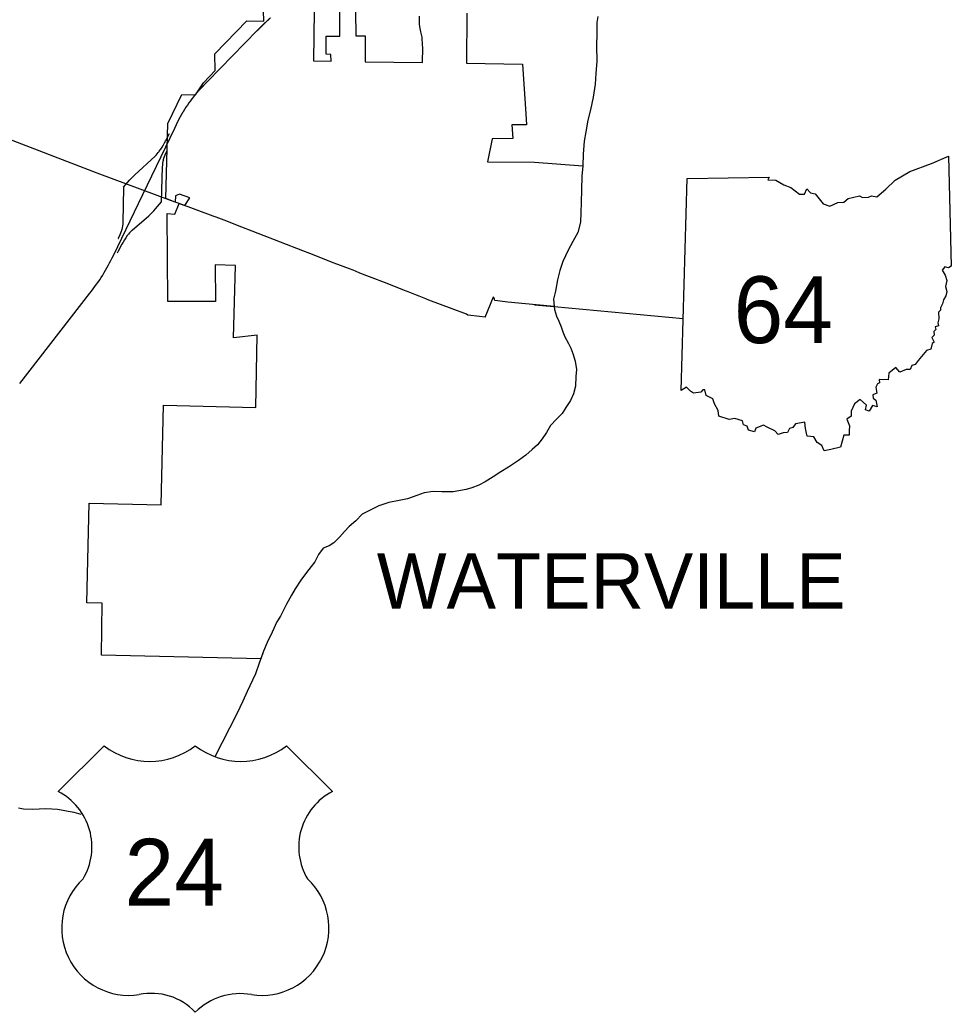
# Model space of a CAD drawing. Extents: x 0 to 750, y 0 to 507.
# Drawn here: x 196.4 to 259.5, y 82 to 149.3 of the extents above; entities that cross this region are included whole.
import ezdxf

# ---------------------------------------------------------------- set-up
doc = ezdxf.new("R2010")
doc.units = 0
for name, color, linetype in [('DV_X_Corp_Line', 7, 'Continuous'), ('GM_X_Corporation_Text', 7, 'Continuous'), ('GM_X_County', 7, 'Continuous'), ('GM_X_Rail_Line', 7, 'Continuous'), ('GM_X_State_Route', 7, 'Continuous'), ('GM_X_US_Route', 7, 'Continuous'), ('PV_P_Text', 7, 'Continuous')]:
    doc.layers.add(name, color=color, linetype=linetype)

msp = doc.modelspace()

# ---------------------------------------------------------------- linework, layer by layer
at = {"layer": 'DV_X_Corp_Line'}
for points in [[(226.679, 149.758), (226.646, 146.356), (230.442, 146.297), (230.68, 142.921), (230.706, 142.191), (229.73, 142.174), (229.795, 141.25), (228.396, 141.225), (228.067, 139.675), (231.248, 139.656), (234.535, 139.41), (234.462, 138.714), (234.446, 137.771), (234.417, 136.918), (234.394, 136.251), (234.376, 135.594), (234.203, 134.894), (233.846, 134.281), (233.544, 133.677), (233.186, 132.909), (232.969, 132.299), (232.806, 131.664), (232.673, 130.908), (232.541, 130.358), (232.595, 129.859), (232.617, 129.656), (232.755, 129.217), (232.895, 128.879), (233.058, 128.484), (233.178, 128.141), (233.323, 127.802), (233.566, 127.361), (233.721, 127.053), (233.865, 126.679), (234.002, 126.169), (234.092, 125.606), (234.069, 125.124), (234.028, 124.467), (233.889, 123.938), (233.695, 123.484), (233.371, 123.013), (233.129, 122.615), (232.756, 122.22), (232.348, 121.795), (232.079, 121.318), (231.766, 120.892), (231.453, 120.495), (231.102, 120.18), (230.669, 119.781), (230.162, 119.428), (229.492, 118.977), (228.98, 118.655), (228.463, 118.317), (227.916, 117.98), (227.481, 117.751), (227.017, 117.573), (226.629, 117.465), (225.754, 117.309), (224.977, 117.307), (224.385, 117.332), (223.787, 117.241), (223.283, 117.054), (222.647, 116.834), (222.094, 116.708), (221.384, 116.569), (220.709, 116.355), (220.077, 116.034), (219.581, 115.781), (219.137, 115.332), (218.69, 114.958), (218.388, 114.617), (218.05, 114.231), (217.653, 113.851), (217.339, 113.646), (216.94, 113.477), (216.621, 113.045), (216.358, 112.563), (216.111, 112.231), (215.803, 111.824), (215.419, 111.309), (215.033, 110.723), (214.79, 110.306), (214.449, 109.689), (214.034, 108.878), (213.801, 108.48), (213.484, 107.793), (213.136, 107.081), (212.9, 106.508), (212.703, 105.974), (201.913, 106.228), (201.947, 109.758), (200.916, 109.782), (201.076, 116.535), (205.953, 116.42), (206.113, 123.173), (212.365, 123.025), (212.465, 127.926), (210.866, 127.753), (210.982, 132.651), (209.607, 132.683), (209.632, 130.207), (206.398, 130.199), (206.351, 136.166), (206.887, 136.133), (207.167, 136.85), (207.565, 136.714), (207.897, 137.23), (207.194, 137.484), (206.928, 137.363), (206.912, 136.944), (206.276, 137.2), (206.401, 142.267), (207.352, 144.24), (208.275, 144.224), (208.822, 145.028), (209.616, 145.87), (209.601, 146.998), (211.749, 149.231), (212.901, 149.215), (212.895, 149.917)], [(216.32, 149.913), (216.28, 146.516), (217.465, 146.497), (217.464, 146.956), (217.132, 146.977), (217.132, 148.197), (218.07, 148.203), (218.074, 149.881)], [(219.129, 149.861), (219.141, 148.21), (219.774, 148.214), (219.774, 148.196), (219.771, 146.462), (223.666, 146.402), (223.681, 147.436), (223.673, 147.594), (223.648, 148.131), (223.552, 148.499), (223.534, 148.591), (223.455, 148.989), (223.455, 149.541)]]:
    msp.add_lwpolyline(points, dxfattribs=at)
at = {"layer": 'GM_X_County'}
for points in [[(235.544, 149.53), (235.492, 149.117), (235.479, 148.399), (235.458, 147.512), (235.492, 146.498), (235.417, 145.661), (235.364, 144.949), (235.224, 144.063), (235.044, 143.212), (234.876, 142.492), (234.742, 141.716), (234.625, 141.085), (234.564, 140.193), (234.535, 139.41), (234.462, 138.714), (234.446, 137.771), (234.417, 136.918), (234.394, 136.251), (234.376, 135.594), (234.203, 134.894), (233.846, 134.281), (233.544, 133.677), (233.186, 132.909), (232.969, 132.299), (232.806, 131.664), (232.673, 130.908), (232.541, 130.358), (232.595, 129.859), (232.617, 129.656), (232.755, 129.217), (232.895, 128.879), (233.058, 128.484), (233.178, 128.141), (233.323, 127.802), (233.566, 127.361), (233.721, 127.053), (233.865, 126.679), (234.002, 126.169), (234.092, 125.606), (234.069, 125.124), (234.028, 124.467), (233.889, 123.938), (233.695, 123.484), (233.371, 123.013), (233.129, 122.615), (232.756, 122.22), (232.348, 121.795), (232.079, 121.318), (231.766, 120.892), (231.453, 120.495), (231.102, 120.18), (230.669, 119.781), (230.162, 119.428), (229.492, 118.977), (228.98, 118.655), (228.463, 118.317), (227.916, 117.98), (227.481, 117.751), (227.017, 117.573), (226.629, 117.465), (225.754, 117.309), (224.977, 117.307), (224.385, 117.332), (223.787, 117.241), (223.283, 117.054), (222.647, 116.834), (222.094, 116.708), (221.384, 116.569), (220.709, 116.355), (220.077, 116.034), (219.581, 115.781), (219.137, 115.332), (218.69, 114.958), (218.388, 114.617), (218.05, 114.231), (217.653, 113.851), (217.339, 113.646), (216.94, 113.477), (216.621, 113.045), (216.358, 112.563), (216.111, 112.231), (215.803, 111.824), (215.419, 111.309), (215.033, 110.723), (214.79, 110.306), (214.449, 109.689), (214.034, 108.878), (213.801, 108.48), (213.484, 107.793), (213.136, 107.081), (212.9, 106.508), (212.596, 105.684), (212.338, 104.961), (212.135, 104.523), (211.781, 103.766), (211.484, 103.103), (211.088, 102.241), (209.591, 99.345)], [(200.534, 95.436), (200.383, 95.471), (200.063, 95.552), (199.647, 95.629), (199.311, 95.705), (198.931, 95.772), (198.534, 95.794), (198.137, 95.806), (197.684, 95.778), (197.212, 95.766), (196.634, 95.781), (196.289, 95.857)]]:
    msp.add_lwpolyline(points, dxfattribs=at)
at = {"layer": 'GM_X_Rail_Line'}
for p, q in [((241.193, 124.183), (241.595, 138.546)), ((241.193, 124.183), (241.595, 138.546)), ((202.086, 100.092), (198.976, 96.982)), ((217.558, 96.982), (214.448, 100.092))]:
    msp.add_line(p, q, dxfattribs=at)
for points in [[(241.595, 138.546), (247.167, 138.64), (247.08, 138.466), (247.606, 138.43), (248.165, 138.123), (248.637, 137.929), (249.215, 137.472), (249.561, 137.477), (249.707, 137.852), (249.972, 137.563), (250.286, 137.511), (250.829, 136.824), (251.277, 136.675), (251.814, 136.911), (252.216, 136.949), (252.509, 137.182), (253.274, 137.381), (253.487, 137.262), (253.892, 137.286), (254.096, 137.374), (254.449, 137.296), (255.071, 137.818), (255.711, 138.434), (256.695, 139.015), (258.165, 139.565), (259.327, 140.057), (259.495, 132.604)], [(241.595, 138.546), (247.167, 138.64), (247.08, 138.466), (247.606, 138.43), (248.165, 138.123), (248.637, 137.929), (249.215, 137.472), (249.561, 137.477), (249.707, 137.852), (249.972, 137.563), (250.286, 137.511), (250.829, 136.824), (251.277, 136.675), (251.814, 136.911), (252.216, 136.949), (252.509, 137.182), (253.274, 137.381), (253.487, 137.262), (253.892, 137.286), (254.096, 137.374), (254.449, 137.296), (255.071, 137.818), (255.711, 138.434), (256.695, 139.015), (258.165, 139.565), (259.327, 140.057), (259.495, 132.604)], [(259.495, 132.604), (259.324, 132.499), (259.057, 132.549), (258.877, 132.339), (259.099, 131.991), (259.204, 131.622), (259.111, 131.216), (259.203, 130.881), (259.141, 130.601), (258.973, 130.322), (258.915, 130.055), (258.772, 129.775), (258.784, 129.618), (258.648, 129.494), (258.672, 129.028), (258.604, 128.77), (258.627, 128.547), (258.407, 128.488), (258.457, 128.304), (258.317, 128.162), (258.347, 127.917), (258.188, 127.761), (258.342, 127.449), (258.218, 127.349), (258.115, 126.969), (257.832, 126.892), (257.265, 126.196), (257.065, 125.934), (256.841, 125.868), (256.717, 125.598), (256.441, 125.597), (256.022, 125.41), (255.751, 125.732), (255.277, 125.344), (255.222, 124.896), (254.623, 124.911), (254.646, 124.684), (254.513, 124.618), (254.391, 124.391), (254.461, 123.988), (254.181, 123.886), (254.215, 123.651), (254.395, 123.508), (254.474, 123.061), (254.176, 123.152), (253.932, 122.775), (253.681, 122.863), (253.763, 123.183), (253.338, 123.567), (252.937, 123.259), (252.727, 122.768), (252.725, 122.437), (252.426, 122.237), (252.617, 121.77), (252.582, 121.448), (252.588, 121.143), (252.214, 121.154), (251.988, 120.329)], [(259.495, 132.604), (259.324, 132.499), (259.057, 132.549), (258.877, 132.339), (259.099, 131.991), (259.204, 131.622), (259.111, 131.216), (259.203, 130.881), (259.141, 130.601), (258.973, 130.322), (258.915, 130.055), (258.772, 129.775), (258.784, 129.618), (258.648, 129.494), (258.672, 129.028), (258.604, 128.77), (258.627, 128.547), (258.407, 128.488), (258.457, 128.304), (258.317, 128.162), (258.347, 127.917), (258.188, 127.761), (258.342, 127.449), (258.218, 127.349), (258.115, 126.969), (257.832, 126.892), (257.265, 126.196), (257.065, 125.934), (256.841, 125.868), (256.717, 125.598), (256.441, 125.597), (256.022, 125.41), (255.751, 125.732), (255.277, 125.344), (255.222, 124.896), (254.623, 124.911), (254.646, 124.684), (254.513, 124.618), (254.391, 124.391), (254.461, 123.988), (254.181, 123.886), (254.215, 123.651), (254.395, 123.508), (254.474, 123.061), (254.176, 123.152), (253.932, 122.775), (253.681, 122.863), (253.763, 123.183), (253.338, 123.567), (252.937, 123.259), (252.727, 122.768), (252.725, 122.437), (252.426, 122.237), (252.617, 121.77), (252.582, 121.448), (252.588, 121.143), (252.214, 121.154), (251.988, 120.329)], [(251.988, 120.329), (251.337, 120.171), (250.886, 120.077), (250.727, 120.452), (250.404, 120.649), (250.194, 121.026), (249.73, 121.078), (249.62, 121.595), (249.568, 122.016), (248.935, 121.912), (248.761, 121.655), (248.536, 121.586), (248.405, 121.327), (248.099, 121.306), (247.77, 121.183), (247.555, 121.437), (247.016, 121.692), (246.774, 121.824), (246.268, 121.619), (246.16, 121.378), (245.756, 121.484), (245.662, 121.754), (245.418, 121.835), (245.364, 122.121), (244.843, 122.273), (244.444, 122.213), (243.74, 122.443), (243.698, 122.819), (243.458, 123.278), (243.333, 123.597), (242.888, 123.84), (242.798, 124.218), (242.656, 124.207), (242.526, 124.053), (242.032, 123.983), (241.835, 124.138), (241.558, 124.402), (241.193, 124.183)], [(251.988, 120.329), (251.337, 120.171), (250.886, 120.077), (250.727, 120.452), (250.404, 120.649), (250.194, 121.026), (249.73, 121.078), (249.62, 121.595), (249.568, 122.016), (248.935, 121.912), (248.761, 121.655), (248.536, 121.586), (248.405, 121.327), (248.099, 121.306), (247.77, 121.183), (247.555, 121.437), (247.016, 121.692), (246.774, 121.824), (246.268, 121.619), (246.16, 121.378), (245.756, 121.484), (245.662, 121.754), (245.418, 121.835), (245.364, 122.121), (244.843, 122.273), (244.444, 122.213), (243.74, 122.443), (243.698, 122.819), (243.458, 123.278), (243.333, 123.597), (242.888, 123.84), (242.798, 124.218), (242.656, 124.207), (242.526, 124.053), (242.032, 123.983), (241.835, 124.138), (241.558, 124.402), (241.193, 124.183)]]:
    msp.add_lwpolyline(points, dxfattribs=at)
for centre, radius, start, end in [((205.177, 104.021), 4.999, 231.81301, 308.18697), ((211.358, 104.021), 4.999, 231.81301, 308.18697), ((197.032, 93.228), 4.228, 329.11751, 62.61081), ((219.503, 93.228), 4.228, 117.38919, 210.88249), ((203.771, 87.722), 4.562, 133.00455, 278.72816), ((212.763, 87.722), 4.562, 261.27184, 46.99545), ((205.303, 79.22), 4.081, 43.41772, 101.87423), ((211.316, 78.949), 4.331, 79.96126, 134.74679)]:
    msp.add_arc(centre, radius, start, end, dxfattribs=at)
at = {"layer": 'GM_X_State_Route'}
for points in [[(201.607, 138.907), (187.574, 144.306)], [(209.486, 135.992), (207.167, 136.85), (206.912, 136.944), (206.656, 137.039), (201.607, 138.907)], [(210.849, 135.473), (210.221, 135.716), (209.685, 135.918), (209.486, 135.992)], [(215.545, 133.651), (211.025, 135.405), (210.849, 135.473)], [(219.367, 132.161), (218.956, 132.321), (218.726, 132.411), (217.688, 132.816), (216.04, 133.459), (215.545, 133.651)], [(222.569, 130.908), (222.444, 130.957), (221.276, 131.416), (220.077, 131.884), (219.425, 132.138), (219.367, 132.161)], [(226.642, 129.338), (225.68, 129.711), (224.102, 130.306), (223.898, 130.386), (223.449, 130.562), (223.252, 130.64), (222.59, 130.9), (222.569, 130.908)], [(230.181, 130.083), (230.177, 130.083), (229.446, 130.168), (228.561, 130.27), (228.544, 130.366), (228.488, 130.513)], [(231.254, 129.984), (231.252, 129.984), (232.595, 129.859), (230.394, 130.063), (230.181, 130.083)], [(232.595, 129.859), (241.329, 129.051)], [(227.924, 129.149), (227.539, 129.198), (226.741, 129.287), (226.642, 129.338)]]:
    msp.add_lwpolyline(points, dxfattribs=at)
at = {"layer": 'GM_X_US_Route'}
for p, q in [((209.113, 145.145), (212.467, 148.57)), ((204.705, 137.453), (206.877, 141.96)), ((204.174, 138.794), (205.537, 140.052)), ((205.986, 136.954), (206.033, 139.331)), ((203.374, 135.569), (203.421, 137.945)), ((203.402, 137.953), (203.815, 138.426)), ((202.717, 133.328), (204.703, 137.45)), ((205.574, 136.484), (205.985, 136.955)), ((203.988, 135.044), (205.112, 136.023)), ((196.376, 124.644), (201.126, 130.761))]:
    msp.add_line(p, q, dxfattribs=at)
msp.add_lwpolyline([(227.924, 129.149), (228.488, 130.513)], dxfattribs=at)
for centre, radius, start, end in [((214.529, 138.965), 8.185, 139.96971, 149.89218), ((197.911, 145.732), 9.549, 325.96496, 334.26718), ((204.242, 141.456), 1.91, 312.69924, 325.96496), ((207.942, 139.294), 1.91, 164.22718, 178.87508), ((207.412, 135.285), 4.775, 132.69924, 138.87508), ((201.977, 139.624), 4.775, 311.04187, 318.87508), ((201.465, 135.606), 1.91, 344.22718, 358.87508), ((211.572, 129.328), 9.549, 145.96496, 154.26718), ((205.242, 133.604), 1.91, 131.04187, 145.96496), ((189.813, 139.547), 14.324, 322.16666, 334.26718)]:
    msp.add_arc(centre, radius, start, end, dxfattribs=at)
for points in [[(212.467, 148.57), (212.479, 148.582), (212.491, 148.594), (212.503, 148.606), (212.515, 148.618), (212.527, 148.63), (212.538, 148.642), (212.55, 148.654), (212.562, 148.666), (212.574, 148.678), (212.586, 148.69), (212.598, 148.702), (212.609, 148.714), (212.621, 148.726), (212.633, 148.738), (212.645, 148.75), (212.657, 148.762), (212.669, 148.774), (212.681, 148.786), (212.692, 148.799), (212.704, 148.811), (212.716, 148.823), (212.728, 148.835), (212.74, 148.846), (212.752, 148.858), (212.764, 148.87), (212.776, 148.882), (212.788, 148.894), (212.8, 148.906), (212.812, 148.918), (212.824, 148.93), (212.836, 148.942), (212.848, 148.954), (212.86, 148.966), (212.872, 148.978), (212.884, 148.99), (212.896, 149.001), (212.908, 149.013), (212.92, 149.025), (212.932, 149.037), (212.944, 149.049), (212.956, 149.061), (212.968, 149.072), (212.98, 149.084), (212.992, 149.096), (213.004, 149.108), (213.017, 149.119), (213.029, 149.131), (213.041, 149.143), (213.053, 149.154), (213.065, 149.166), (213.078, 149.178), (213.09, 149.189), (213.102, 149.201), (213.114, 149.212), (213.127, 149.224), (213.139, 149.236), (213.151, 149.247), (213.164, 149.259), (213.176, 149.27), (213.189, 149.282), (213.201, 149.293), (213.213, 149.304), (213.226, 149.316), (213.238, 149.327), (213.251, 149.339), (213.263, 149.35), (213.276, 149.361), (213.289, 149.373), (213.301, 149.384), (213.314, 149.395), (213.326, 149.406), (213.339, 149.418), (213.352, 149.429), (213.364, 149.44)], [(208.261, 144.23), (208.272, 144.243), (208.283, 144.256), (208.294, 144.269), (208.305, 144.281), (208.316, 144.294), (208.327, 144.307), (208.338, 144.32), (208.349, 144.333), (208.36, 144.345), (208.371, 144.358), (208.382, 144.371), (208.394, 144.383), (208.405, 144.396), (208.416, 144.409), (208.427, 144.421), (208.438, 144.434), (208.45, 144.447), (208.461, 144.459), (208.472, 144.472), (208.483, 144.484), (208.495, 144.497), (208.506, 144.509), (208.518, 144.522), (208.529, 144.534), (208.54, 144.547), (208.552, 144.559), (208.563, 144.572), (208.575, 144.584), (208.586, 144.597), (208.598, 144.609), (208.609, 144.621), (208.621, 144.634), (208.632, 144.646), (208.644, 144.658), (208.655, 144.671), (208.667, 144.683), (208.678, 144.695), (208.69, 144.708), (208.702, 144.72), (208.713, 144.732), (208.725, 144.744), (208.736, 144.757), (208.748, 144.769), (208.76, 144.781), (208.771, 144.793), (208.783, 144.805), (208.795, 144.818), (208.806, 144.83), (208.818, 144.842), (208.83, 144.854), (208.842, 144.866), (208.853, 144.878), (208.865, 144.891), (208.877, 144.903), (208.889, 144.915), (208.9, 144.927), (208.912, 144.939), (208.924, 144.951), (208.936, 144.963), (208.947, 144.975), (208.959, 144.988), (208.971, 145), (208.983, 145.012), (208.995, 145.024), (209.006, 145.036), (209.018, 145.048), (209.03, 145.06), (209.042, 145.072), (209.054, 145.084), (209.066, 145.096), (209.077, 145.108), (209.089, 145.12), (209.101, 145.132), (209.113, 145.145)], [(206.877, 141.96), (206.884, 141.975), (206.892, 141.99), (206.899, 142.005), (206.906, 142.02), (206.914, 142.036), (206.921, 142.051), (206.928, 142.066), (206.936, 142.081), (206.943, 142.096), (206.95, 142.112), (206.958, 142.127), (206.965, 142.142), (206.972, 142.157), (206.98, 142.172), (206.987, 142.188), (206.995, 142.203), (207.002, 142.218), (207.009, 142.233), (207.017, 142.248), (207.024, 142.264), (207.032, 142.279), (207.039, 142.294), (207.046, 142.309), (207.054, 142.324), (207.061, 142.339), (207.069, 142.355), (207.076, 142.37), (207.084, 142.385), (207.091, 142.4), (207.099, 142.415), (207.106, 142.43), (207.114, 142.445), (207.121, 142.46), (207.129, 142.476), (207.137, 142.491), (207.144, 142.506), (207.152, 142.521), (207.159, 142.536), (207.167, 142.551), (207.175, 142.566), (207.182, 142.581), (207.19, 142.596), (207.198, 142.611), (207.206, 142.626), (207.213, 142.641), (207.221, 142.656), (207.229, 142.671), (207.237, 142.686), (207.245, 142.701), (207.252, 142.716), (207.26, 142.731), (207.268, 142.746), (207.276, 142.761), (207.284, 142.776), (207.292, 142.791), (207.3, 142.806), (207.308, 142.82), (207.316, 142.835), (207.324, 142.85), (207.332, 142.865), (207.34, 142.88), (207.348, 142.895), (207.356, 142.909), (207.365, 142.924), (207.373, 142.939), (207.381, 142.954), (207.389, 142.968), (207.398, 142.983), (207.406, 142.998), (207.414, 143.013), (207.423, 143.027), (207.431, 143.042), (207.439, 143.056), (207.448, 143.071)], [(206.104, 139.813), (206.107, 139.822), (206.109, 139.83), (206.112, 139.839), (206.114, 139.848), (206.117, 139.856), (206.12, 139.865), (206.122, 139.873), (206.125, 139.882), (206.128, 139.89), (206.131, 139.899), (206.133, 139.907), (206.136, 139.916), (206.139, 139.924), (206.142, 139.933), (206.145, 139.941), (206.148, 139.95), (206.151, 139.958), (206.154, 139.967), (206.157, 139.975), (206.16, 139.984), (206.163, 139.992), (206.167, 140), (206.17, 140.009), (206.173, 140.017), (206.176, 140.025), (206.18, 140.034), (206.183, 140.042), (206.186, 140.05), (206.19, 140.059), (206.193, 140.067), (206.196, 140.075), (206.2, 140.084), (206.203, 140.092), (206.207, 140.1), (206.21, 140.109), (206.214, 140.117), (206.217, 140.125), (206.221, 140.133), (206.224, 140.141), (206.228, 140.15), (206.232, 140.158), (206.235, 140.166), (206.239, 140.174), (206.243, 140.183), (206.246, 140.191), (206.25, 140.199), (206.254, 140.207), (206.257, 140.215), (206.261, 140.223), (206.265, 140.232), (206.269, 140.24), (206.272, 140.248), (206.276, 140.256), (206.28, 140.264), (206.284, 140.272), (206.287, 140.28), (206.291, 140.289), (206.295, 140.297), (206.299, 140.305), (206.303, 140.313), (206.307, 140.321), (206.31, 140.329), (206.314, 140.337), (206.318, 140.345), (206.322, 140.353), (206.326, 140.361), (206.33, 140.37), (206.334, 140.378), (206.338, 140.386), (206.342, 140.394), (206.345, 140.402), (206.349, 140.41), (206.353, 140.418), (206.357, 140.426)], [(203.05, 134.474), (203.054, 134.482), (203.058, 134.49), (203.061, 134.498), (203.065, 134.506), (203.069, 134.514), (203.073, 134.522), (203.077, 134.53), (203.081, 134.539), (203.085, 134.547), (203.089, 134.555), (203.093, 134.563), (203.096, 134.571), (203.1, 134.579), (203.104, 134.587), (203.108, 134.595), (203.112, 134.603), (203.116, 134.612), (203.119, 134.62), (203.123, 134.628), (203.127, 134.636), (203.131, 134.644), (203.135, 134.652), (203.138, 134.66), (203.142, 134.668), (203.146, 134.677), (203.15, 134.685), (203.153, 134.693), (203.157, 134.701), (203.161, 134.709), (203.164, 134.717), (203.168, 134.726), (203.172, 134.734), (203.175, 134.742), (203.179, 134.75), (203.182, 134.759), (203.186, 134.767), (203.19, 134.775), (203.193, 134.783), (203.197, 134.792), (203.2, 134.8), (203.204, 134.808), (203.207, 134.816), (203.21, 134.825), (203.214, 134.833), (203.217, 134.841), (203.221, 134.85), (203.224, 134.858), (203.227, 134.866), (203.231, 134.875), (203.234, 134.883), (203.237, 134.891), (203.24, 134.9), (203.243, 134.908), (203.247, 134.916), (203.25, 134.925), (203.253, 134.933), (203.256, 134.942), (203.259, 134.95), (203.262, 134.959), (203.265, 134.967), (203.268, 134.976), (203.271, 134.984), (203.273, 134.993), (203.276, 135.001), (203.279, 135.01), (203.282, 135.018), (203.285, 135.027), (203.287, 135.035), (203.29, 135.044), (203.293, 135.052), (203.295, 135.061), (203.298, 135.07), (203.3, 135.078), (203.303, 135.087)]]:
    msp.add_spline(points, degree=3, dxfattribs=at)

# ---------------------------------------------------------------- texts
at = {"layer": 'GM_X_Corporation_Text'}
msp.add_text('WATERVILLE', height=3.7501, rotation=0.00001, dxfattribs=at).set_placement((220.567, 109.391))
at = {"layer": 'GM_X_Rail_Line'}
msp.add_text('64', height=4.5281, dxfattribs=at).set_placement((244.752, 127.386))
at = {"layer": 'PV_P_Text'}
msp.add_text('24', height=4.5281, dxfattribs=at).set_placement((203.471, 89.249))

doc.saveas('drawing.dxf')
